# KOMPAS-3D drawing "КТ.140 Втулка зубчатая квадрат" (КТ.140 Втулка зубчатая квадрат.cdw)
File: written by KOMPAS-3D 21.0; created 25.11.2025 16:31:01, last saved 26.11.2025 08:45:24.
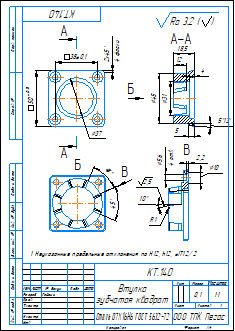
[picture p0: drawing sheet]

Sheet 1: A4, portrait

Document properties: Автор: User; Организация: User; Знак неуказанной шероховатости: 4; Параметр неуказанной шероховатости: Ra 3.2; Масса: 0.101259

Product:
- Part/product: КТ.140 Втулка зубчатая квадрат
    Масса: 0.101259
    Комментарий: User

Title block, sheet 1: Наименование: Втулка / зубчатая квадрат; designation: КТ.140; Материал: Сталь 07Х16Н6 ГОСТ 5632-72; Масса: 0,1; Количество листов документа: 1; organisation: ООО ТПК Пегас; Форматы листов документа: A4; stored path: C:\Users\User\Desktop\Pelorus PRO доработки\ЗАФИКСИРОВАЛИ\Втулка зубчатая квадрат\КТ.140 Втулка зубчатая квадрат.cdw; Разработал: Гайсин

Views: Вид 1, Снизу, Разрез А-А, Вид по стрелке А, Вид по стрелке Б, Вид по стрелке В
Referenced files in C:\Users\User\Desktop\Pelorus PRO доработки\ЗАФИКСИРОВАЛИ\Втулка зубчатая квадрат\: КТ.140 Втулка зубчатая квадрат.m3d
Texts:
  КТ.140 Втулка зубчатая квадрат
  Ra 3.2
  Ra 3.2 ( )
Dimensions and other numbers on the sheet: 50; 38±0,1; 37; 2; 4 фаски; 7; 18,5; 5 13'; 5; 31; 45; 4; 12; 1:1; 1; 0,1

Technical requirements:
  Неуказанные предельные отклонения по H12, h12,  IT12/2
